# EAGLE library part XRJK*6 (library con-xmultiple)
RJ11 Connector without LED, 6 position, 6 contacts, shielded, thrue hole Source: XRJK-S-01-6-6-0-2G2-NO(01).pdf
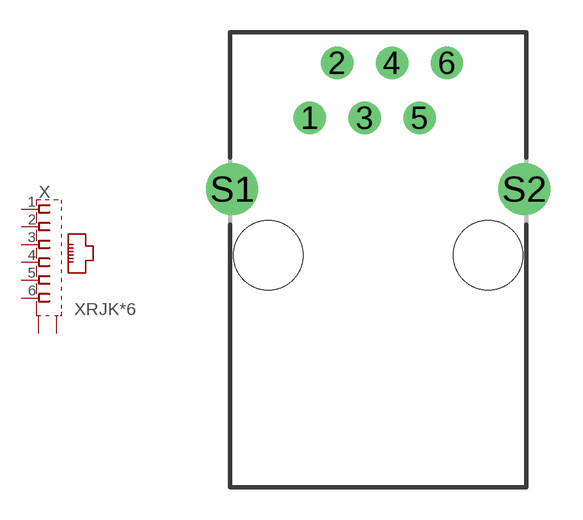
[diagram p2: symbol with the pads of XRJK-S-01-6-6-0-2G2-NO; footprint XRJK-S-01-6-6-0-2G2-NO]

Designator prefix X

## XRJK-S-01-6-6-0-2G2-NO  [XRJK-S-01-6-6-0-2G2-NO]
1  1  pas
2  2  pas
3  3  pas
4  4  pas
5  5  pas
6  6  pas
S1  S  pas
S2  S  pas

## Footprint XRJK-S-01-6-6-0-2G2-NO (pad centres in mm)
RJ11 Connector without LED, 6 position, 6 contacts, shielded, thrue hole Source: XRJK-S-01-6-6-0-2G2-NO(01).pdf
drill 0.9 pad 1.5 round: 1 -3.175,6.35; 2 -1.905,8.89; 3 -0.635,6.35; 4 0.635,8.89; 5 1.905,6.35; 6 3.175,8.89
drill 1.6 pad 2.184 round: S1 -6.75,3.05; S2 6.75,3.05
hole 3.2 at -5.08,0
hole 3.2 at 5.08,0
